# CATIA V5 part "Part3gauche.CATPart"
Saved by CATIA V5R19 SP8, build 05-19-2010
Part number: Part3.1
Bounding box of the stored display mesh (mm): x 0 to 632, y 0 to 592, z 0 to 200
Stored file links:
  G:\EU_thinkMotion\CFAO_2010\SIL_groupe2\SIL_groupe2\A reprendre\fnongaibaa\fnongaibaa\Part3gauche.CATPart
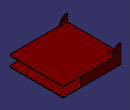
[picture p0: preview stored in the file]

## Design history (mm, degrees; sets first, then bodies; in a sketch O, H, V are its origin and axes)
Body1 (main body)
  Sketch1 on xy-plane, origin (0, 0, 0), H (1, 0, 0), V (0, 1, 0)
    line L1 (0, 592) -> (632, 592)
    line L2 (632, 592) -> (632, 0)
    line L3 (632, 0) -> (0, 0)
    line L4 (0, 0) -> (0, 592)
    point P3 (632, 0)
    length L3 = 632
    length L2 = 592
    horizontal: L1 H, L3 H
    vertical: L2 V, L4 V
    coincidence: P3 H
  Pad1: profile Sketch1, direction (0, 0, 1), length 110
  Fillet1: radius 20, on edge [face of Pad1 from Sketch1.L2 | face of Pad1 from Sketch1.L3]
  Sketch2 on face of Pad1 from Sketch1.L2, origin (632, 0, 0), H (0, 1, 0), V (0, 0, 1)
    line L1 (-40, 105) -> (650, 105)
    line L2 (-40, 5) -> (650, 5)
    reference projected line E1 (0, 0) -> (632, 0) from edge [start face of Pad1 | face of Pad1 from Sketch1.L2]
    reference projected line E2 (0, 110) -> (632, 110) from edge [face of Pad1 from Sketch1.L2 | end face of Pad1]
    line L3 (-40, 5) -> (-40, 105)
    line L4 (650, 5) -> (650, 105)
    distance L2 E1 = 5
    distance L1 E2 = 5
    horizontal: L1 H, L2 H
    vertical: L3 V, L4 V
  Pocket1: profile Sketch2, direction (-1, 0, 0), length 200
  Sketch3 on end face of Pad1, origin (415.2374, 227.835, 110), H (1, 0, 0), V (0, 1, 0)
    point P1 (-350.2374, 299.165)
    reference projected line E1 (-415.2374, 404.165) -> (-415.2374, -227.835) from edge [face of Pad1 | end face of Pad1]
    reference projected line E2 (216.7626, 364.165) -> (-415.2374, 364.165) from edge [face of Pad1 | end face of Pad1]
    distance P1 E1 = 65
    distance P1 E2 = 65
  Hole1: placed by Sketch3, at (65, 527, 110) direction (0, 0, -1), diameter 20, through (limit type 3)
  Sketch4 on end face of Pocket1, origin (432, 0, 0), H (0, 1, 0), V (0, 0, 1)
    line L1 (0, 105) -> (587, 105)
    line L2 (587, 105) -> (587, 5)
    line L3 (587, 5) -> (0, 5)
    line L4 (0, 5) -> (0, 105)
    reference projected line E1 (650, 105) -> (-40, 105) from edge [end face of Pocket1 | face of Pocket1 from Sketch2.L1]
    reference projected line E2 (-40, 5) -> (650, 5) from edge [end face of Pocket1 | face of Pocket1 from Sketch2.L2]
    reference projected line E3 (0, 105) -> (0, 5) from edge [face of Pad1 from Sketch1.L3 | end face of Pocket1]
    reference projected line E4 (592, 105) -> (592, 5) from edge [end face of Pocket1 | face of Pad1 from Sketch1.L1]
    distance L2 E4 = 5
    horizontal: L1 H, L3 H
    vertical: L2 V, L4 V
    coincidence: L1 E1, L3 E2, L4 E3
  Pocket2: profile Sketch4, direction (-1, 0, 0), length 400
  Sketch5 on end face of Pad1, origin (0, 0, 110), H (1, 0, 0), V (0, 1, 0)
    line L1 (0, 10) -> (80, 10)
    line L2 (80, 10) -> (80, 0)
    line L3 (80, 0) -> (0, 0)
    line L4 (0, 0) -> (0, 10)
    reference projected line E1 (0, 632) -> (0, 0) from edge [face of Pad1 from Sketch1.L4 | end face of Pad1]
    reference projected line E2 (0, 0) -> (632, 0) from edge [face of Pad1 from Sketch1.L3 | end face of Pad1]
    length L3 = 80
    length L4 = 10
    horizontal: L1 H, L3 H
    vertical: L2 V, L4 V
    coincidence: L4 E1, L3 E2
  Shaft1: profile Sketch5, axis Sketch5.L4, angle 90
  Sketch6 on end face of Pad1, origin (0, 0, 110), H (1, 0, 0), V (0, 1, 0)
    line L1 (0, 592) -> (90, 592)
    line L2 (90, 592) -> (90, 582)
    line L3 (90, 582) -> (0, 582)
    line L4 (0, 582) -> (0, 592)
    reference projected line E1 (632, 592) -> (0, 592) from edge [face of Pad1 from Sketch1.L1 | end face of Pad1]
    reference projected line E2 (0, 632) -> (0, 0) from edge [face of Shaft1 | end face of Pad1]
    length L4 = 10
    length L1 = 90
    horizontal: L1 H, L3 H
    vertical: L2 V, L4 V
    coincidence: L1 E1, L4 E2
  Shaft2: profile Sketch6, axis Sketch6.L4, angle 90
  Sketch7 on face of Shaft1, origin (30.9379, 0, 142.1656), H (1, 0, 0), V (0, 0, 1)
    point P1 (4.0621, 2.8344)
    reference projected line E1 (-30.9379, -32.1656) -> (601.0621, -32.1656) from edge [face of Shaft1 | end face of Pad1]
    reference projected line E2 (-30.9379, -142.1656) -> (-30.9379, -32.1656) from edge [face of Shaft1 | face of Shaft2]
    distance P1 E1 = 35
    distance P1 E2 = 35
  Hole2: placed by Sketch7, at (35, 0, 145) direction (0, 1, 0), diameter 20, through (limit type 3)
